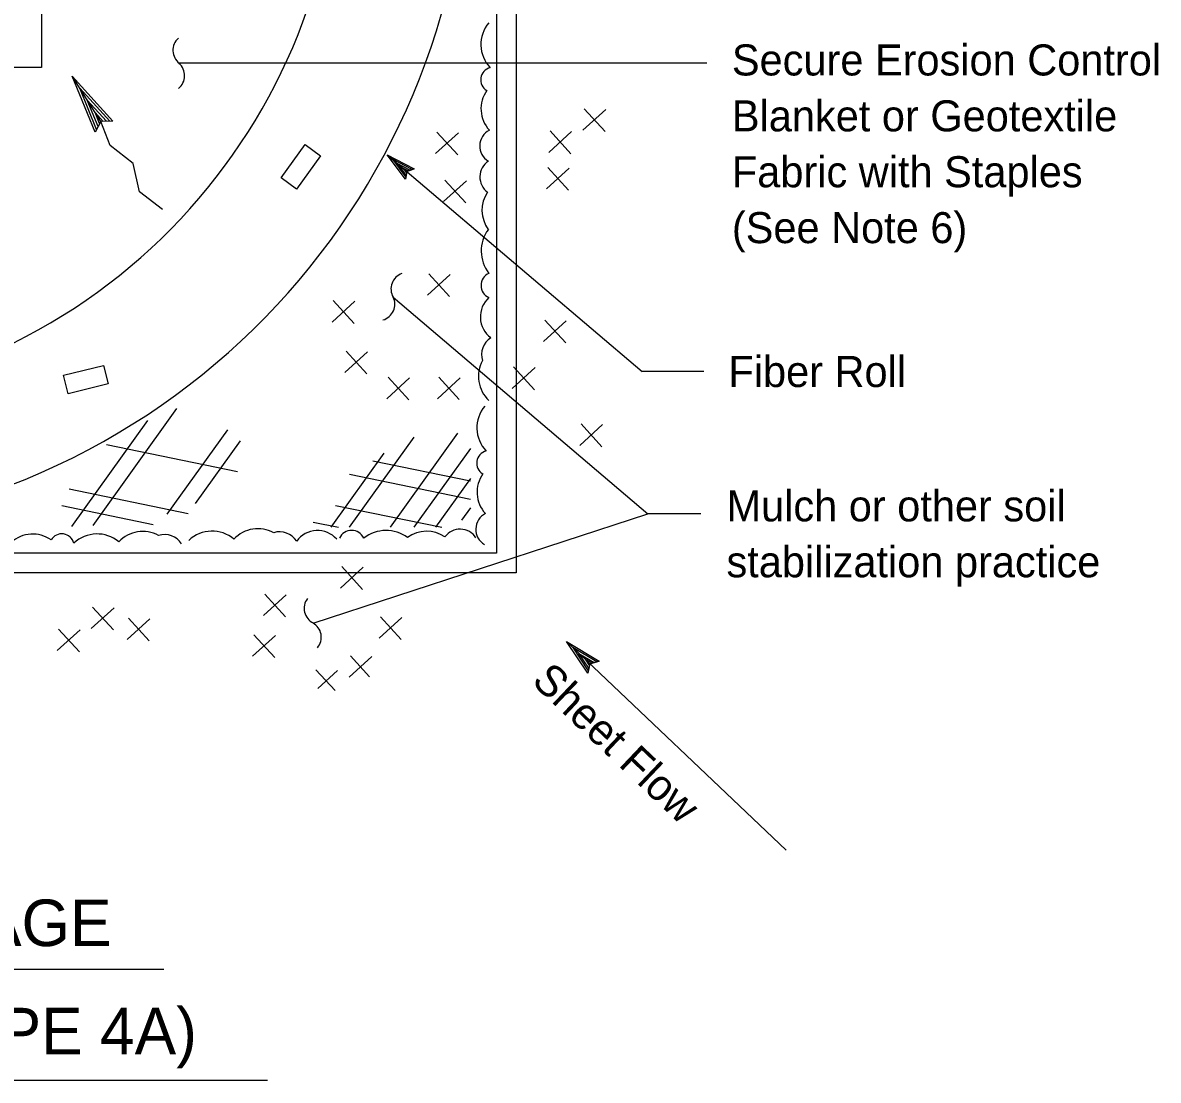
# Model space of a CAD drawing. Extents: x 6708945 to 6710368, y 1871409 to 1872338.
# Drawn here: x 6709235.1 to 6709454.6, y 1871430 to 1871634.3 of the extents above; entities that cross this region are included whole.
import ezdxf

# ---------------------------------------------------------------- set-up
doc = ezdxf.new("R2010")
doc.units = 0
for name, color, linetype in [('1 Control', 7, 'Continuous'), ('57 Undefined', 7, 'Continuous'), ('60 Nongeo Data', 7, 'Continuous'), ('62 As-Built Chng', 7, 'Continuous'), ('63 Undefined', 7, 'Continuous')]:
    doc.layers.add(name, color=color, linetype=linetype)

msp = doc.modelspace()

# ---------------------------------------------------------------- linework, layer by layer
at = {"layer": '1 Control'}
for p, q in [((6709340.19, 1871514.73), (6709340.19, 1871514.73)), ((6709346.51, 1871510.93), (6709346.51, 1871510.93)), ((6709344.3, 1871508.61), (6709344.3, 1871508.61))]:
    msp.add_line(p, q, dxfattribs=at)
msp.add_lwpolyline([(6709344.3, 1871508.61), (6709340.19, 1871514.73), (6709346.51, 1871510.93), (6709346.03, 1871510.8), (6709341.4, 1871513.58), (6709344.41, 1871509.09), (6709344.52, 1871509.57), (6709342.59, 1871512.44), (6709345.55, 1871510.67), (6709345.07, 1871510.53), (6709343.79, 1871511.3), (6709344.63, 1871510.06), (6709344.71, 1871510.43), (6709346.51, 1871510.93), (6709344.71, 1871510.43)], close=True, dxfattribs=at)
at = {"layer": '57 Undefined'}
for p, q in [((6709367.3, 1871626.48), (6709265.36, 1871626.48)), ((6709305.54, 1871608.8), (6709354.79, 1871566.89)), ((6709306.68, 1871581.3), (6709355.94, 1871539.39)), ((6709366.73, 1871566.89), (6709354.79, 1871566.89)), ((6709291.22, 1871518.28), (6709355.94, 1871539.39)), ((6709366.16, 1871539.39), (6709355.94, 1871539.39)), ((6709382.64, 1871474.43), (6709340.19, 1871514.73)), ((6709107.16, 1871451.4), (6709262.36, 1871451.4)), ((6709088.47, 1871429.96), (6709282.38, 1871429.96))]:
    msp.add_line(p, q, dxfattribs=at)
at = {"layer": '60 Nongeo Data'}
for p, q in [((6709305.54, 1871608.8), (6709305.54, 1871608.8)), ((6709310.75, 1871606.04), (6709310.75, 1871606.04)), ((6709309.09, 1871604.09), (6709309.09, 1871604.09))]:
    msp.add_line(p, q, dxfattribs=at)
msp.add_lwpolyline([(6709309.09, 1871604.09), (6709305.54, 1871608.8), (6709310.75, 1871606.04), (6709310.38, 1871605.92), (6709306.56, 1871607.94), (6709309.16, 1871604.48), (6709309.22, 1871604.87), (6709307.56, 1871607.08), (6709310, 1871605.79), (6709309.62, 1871605.66), (6709308.57, 1871606.22), (6709309.29, 1871605.27), (6709309.34, 1871605.57), (6709310.75, 1871606.04), (6709309.34, 1871605.57)], close=True, dxfattribs=at)
msp.add_arc((6709182.99, 1871674.08), 113.4, 20.4401, 11.3417, dxfattribs=at)
at = {"layer": '62 As-Built Chng'}
for p, q in [((6709343.62, 1871617.65), (6709347.64, 1871613.26)), ((6709343.37, 1871613.51), (6709347.77, 1871617.53)), ((6709315.15, 1871613.16), (6709319.17, 1871608.76)), ((6709336.79, 1871609.25), (6709341.19, 1871613.27)), ((6709337.04, 1871613.4), (6709341.06, 1871609)), ((6709314.9, 1871609.01), (6709319.3, 1871613.03)), ((6709336.32, 1871602.2), (6709340.72, 1871606.21)), ((6709336.57, 1871606.34), (6709340.59, 1871601.94)), ((6709316.45, 1871599.73), (6709320.85, 1871603.75)), ((6709316.7, 1871603.87), (6709320.72, 1871599.47)), ((6709313.34, 1871581.63), (6709317.74, 1871585.65)), ((6709313.59, 1871585.77), (6709317.61, 1871581.38)), ((6709294.88, 1871576.47), (6709299.28, 1871580.49)), ((6709295.13, 1871580.61), (6709299.15, 1871576.21)), ((6709335.77, 1871572.69), (6709340.16, 1871576.7)), ((6709336.02, 1871576.83), (6709340.04, 1871572.43)), ((6709297.34, 1871566.69), (6709301.74, 1871570.71)), ((6709297.59, 1871570.84), (6709301.61, 1871566.44)), ((6709329.72, 1871563.65), (6709334.12, 1871567.67)), ((6709329.97, 1871567.8), (6709333.99, 1871563.4)), ((6709305.46, 1871561.66), (6709309.86, 1871565.68)), ((6709305.71, 1871565.81), (6709309.73, 1871561.41)), ((6709315.27, 1871561.64), (6709319.67, 1871565.66)), ((6709315.52, 1871565.79), (6709319.43, 1871561.51)), ((6709342.76, 1871552.63), (6709347.16, 1871556.65)), ((6709343.01, 1871556.77), (6709347.03, 1871552.38)), ((6709296.5, 1871525.07), (6709300.89, 1871529.08)), ((6709296.75, 1871529.21), (6709300.77, 1871524.81)), ((6709281.63, 1871519.76), (6709286.03, 1871523.78)), ((6709281.88, 1871523.91), (6709285.9, 1871519.51)), ((6709248.36, 1871517.25), (6709252.76, 1871521.27)), ((6709248.61, 1871521.39), (6709252.63, 1871516.99)), ((6709255.28, 1871515.13), (6709259.68, 1871519.15)), ((6709255.53, 1871519.28), (6709259.55, 1871514.88)), ((6709304, 1871515.37), (6709308.39, 1871519.39)), ((6709304.25, 1871519.51), (6709308.27, 1871515.11)), ((6709241.79, 1871512.99), (6709246.19, 1871517.01)), ((6709242.04, 1871517.14), (6709246.06, 1871512.74)), ((6709279.54, 1871511.88), (6709283.94, 1871515.9)), ((6709279.79, 1871516.02), (6709283.81, 1871511.62)), ((6709298.2, 1871507.84), (6709302.6, 1871511.86)), ((6709298.45, 1871511.99), (6709302.15, 1871507.94)), ((6709291.78, 1871509.27), (6709295.46, 1871505.25)), ((6709292.12, 1871505.66), (6709295.93, 1871509.15))]:
    msp.add_line(p, q, dxfattribs=at)
for points in [[(6709036.13, 1871820.42), (6709330.46, 1871820.42), (6709330.46, 1871528.03), (6709036.13, 1871528.03)], [(6709040.24, 1871816.63), (6709326.68, 1871816.63), (6709326.68, 1871531.81), (6709040.24, 1871531.81)], [(6709126.63, 1871723.85), (6709238.71, 1871723.85), (6709238.71, 1871625.65), (6709126.63, 1871625.65)], [(6709288.02, 1871602.16), (6709285.03, 1871604.32), (6709289.68, 1871610.76), (6709292.67, 1871608.6)], [(6709243.91, 1871562.59), (6709243.01, 1871566.17), (6709250.72, 1871568.1), (6709251.62, 1871564.52)]]:
    msp.add_lwpolyline(points, close=True, dxfattribs=at)
msp.add_arc((6709182.99, 1871674.08), 138.36, 19.738, 11.782, dxfattribs=at)
at = {"layer": '63 Undefined'}
for p, q in [((6709249.1, 1871613.13), (6709244.64, 1871623.96)), ((6709244.64, 1871623.96), (6709252.54, 1871615.31)), ((6709249.38, 1871613.68), (6709246.11, 1871621.63)), ((6709246.11, 1871621.63), (6709251.92, 1871615.29)), ((6709249.68, 1871614.24), (6709247.58, 1871619.32)), ((6709247.58, 1871619.32), (6709251.28, 1871615.26)), ((6709249.97, 1871614.8), (6709249.09, 1871616.95)), ((6709249.09, 1871616.95), (6709250.65, 1871615.24)), ((6709250.19, 1871615.21), (6709249.1, 1871613.13)), ((6709252.54, 1871615.31), (6709250.19, 1871615.21)), ((6709264.85, 1871559.73), (6709248.67, 1871537.17)), ((6709259.22, 1871557.42), (6709244.55, 1871536.96)), ((6709274.66, 1871555.67), (6709262.96, 1871539.35)), ((6709310.69, 1871554.25), (6709298.19, 1871536.82)), ((6709319.12, 1871554.97), (6709306.11, 1871536.82)), ((6709251.31, 1871552.8), (6709276.6, 1871547.61)), ((6709277.14, 1871553.49), (6709268.45, 1871541.38)), ((6709321.62, 1871552.05), (6709310.71, 1871536.82)), ((6709304.89, 1871551.1), (6709294.66, 1871536.82)), ((6709302.78, 1871549.63), (6709321.62, 1871545.76)), ((6709298.28, 1871547.05), (6709321.62, 1871542.26)), ((6709321.62, 1871546.22), (6709314.89, 1871536.82)), ((6709244.06, 1871544.21), (6709267.08, 1871539.49)), ((6709242.68, 1871540.99), (6709260.34, 1871537.37)), ((6709295.53, 1871541.04), (6709316.1, 1871536.82)), ((6709321.62, 1871540.59), (6709319.92, 1871538.21)), ((6709291.25, 1871537.82), (6709296.13, 1871536.82))]:
    msp.add_line(p, q, dxfattribs=at)
msp.add_lwpolyline([(6709262.12, 1871598.19), (6709257.68, 1871601.63), (6709256.46, 1871607.11), (6709252.02, 1871610.55), (6709250.19, 1871615.21), (6709244.64, 1871623.96)], dxfattribs=at)
for centre, radius, start, end in [((6709330.2, 1871630.1), 6.54, 139.9986, 223.3536), ((6709267.27, 1871628.97), 3.14, 131.7958, 232.6062), ((6709263.26, 1871624.07), 3.14, 308.6008, 49.4112), ((6709326.02, 1871623.28), 2.4, 104.0578, 239.3233), ((6709329.77, 1871617.68), 6.1, 144.5002, 222.8354), ((6709326.84, 1871610.49), 3.41, 117.0211, 239.1913), ((6709327.14, 1871604.5), 3.68, 123.6905, 233.3403), ((6709330.06, 1871598.06), 6.2, 145.656, 216.6973), ((6709330.71, 1871590.18), 7, 143.3979, 217.9353), ((6709309.41, 1871582.85), 3.14, 108.8692, 209.6796), ((6709326.26, 1871583.53), 2.57, 114.5196, 245.4804), ((6709303.88, 1871579.9), 3.14, 285.6742, 26.4846), ((6709328.54, 1871577.48), 5, 132.1292, 233.705), ((6709327.66, 1871570.17), 3.88, 122.3474, 197.3796), ((6709329.54, 1871565.96), 6.36, 151.3634, 226.8458), ((6709329.42, 1871556.03), 6.54, 139.9986, 223.3536), ((6709325.25, 1871549.21), 2.4, 104.0578, 239.3233), ((6709329, 1871543.61), 6.1, 144.5002, 222.8354), ((6709326.07, 1871536.42), 3.41, 117.0211, 239.1913), ((6709280.56, 1871530.18), 6.36, 61.3634, 136.8458), ((6709319.64, 1871532.76), 3.68, 33.6905, 143.3403), ((6709237.04, 1871529.41), 6.1, 54.5002, 132.8354), ((6709242.64, 1871533.15), 2.4, 14.0578, 149.3233), ((6709249.46, 1871528.98), 6.54, 49.9986, 133.3536), ((6709258.3, 1871529.64), 6.36, 61.3634, 136.8458), ((6709262.51, 1871531.52), 3.88, 32.3474, 107.3796), ((6709271.71, 1871529.52), 6.54, 49.9986, 133.3536), ((6709284.77, 1871532.06), 3.88, 32.3474, 107.3796), ((6709292.08, 1871531.18), 5, 42.1292, 143.705), ((6709298.67, 1871533.64), 2.57, 24.5196, 155.4804), ((6709305.32, 1871529.19), 7, 53.3979, 127.9353), ((6709313.2, 1871529.84), 6.2, 55.656, 126.6973), ((6709292.63, 1871521.15), 3.14, 143.1107, 243.9212), ((6709289.67, 1871515.57), 3.14, 319.9157, 60.7262)]:
    msp.add_arc(centre, radius, start, end, dxfattribs=at)

# ---------------------------------------------------------------- texts
at = {"layer": '57 Undefined'}
for s, height, p in [('Secure Erosion Control ', 6, (6709372.16, 1871624.11)), ('Blanket or Geotextile', 6, (6709372.16, 1871613.31)), ('Fabric with Staples ', 6, (6709372.16, 1871602.51)), ('(See Note 6)', 6, (6709372.16, 1871591.71)), ('Fiber Roll', 6, (6709371.49, 1871563.91)), ('Mulch or other soil ', 6, (6709371.12, 1871537.95)), ('stabilization practice', 6, (6709371.12, 1871527.15)), ('TEMPORARY DRAINAGE', 9, (6709109.83, 1871455.88)), ('INLET PROTECTION (TYPE 4A)', 9, (6709091.56, 1871434.96))]:
    msp.add_text(s, height=height, dxfattribs=at).set_placement(p)
msp.add_text('Sheet Flow', height=6, rotation=316.4904, dxfattribs=at).set_placement((6709333.24, 1871506.8))

doc.saveas('drawing.dxf')
